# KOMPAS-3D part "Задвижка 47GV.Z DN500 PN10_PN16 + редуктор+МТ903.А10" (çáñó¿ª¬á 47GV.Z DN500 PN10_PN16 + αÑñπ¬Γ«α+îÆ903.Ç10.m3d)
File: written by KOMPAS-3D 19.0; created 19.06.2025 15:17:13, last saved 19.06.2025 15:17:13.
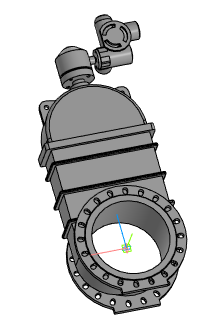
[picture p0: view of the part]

Document properties: Полное имя файла: Задвижка 47GV.Z DN500 PN10_PN16 + редуктор+МТ903.А10.a3d

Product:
- Part/product: Задвижка 47GV.Z DN500 PN10_PN16 + редуктор+МТ903.А10
    Масса: 1324.65

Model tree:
1. Операция без истории:1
